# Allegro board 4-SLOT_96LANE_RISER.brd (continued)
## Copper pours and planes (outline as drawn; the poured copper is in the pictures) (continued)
P3V3 on TOP (solid shape): 289,96.77 289,96.74 288.85,96.23 288.99,95.71 289,95.69 289,95.5 288.68,95.18 288.66,95.18 287.85,94.27 288.55,93.28 288.57,93.27 288.88,92.96 288.88,92.7 288.88,91.95 288.75,91.82 284.3,91.82 284.23,91.9 284.23,93.37 286.72,95.86 286.72,96.82 286.97,97.08 288.7,97.08
P3V3 on TOP (solid shape): 288.62,76.33 288.62,74.91 288.61,74.86 288.57,74.84 287.86,74.01 288.34,73.04 288.35,73.04 288.86,72.53 288.86,71.5 288.74,71.37 282.91,71.37 282.84,71.44 282.84,71.92 285.97,75.06 285.98,75.06 286.21,75.06 286.46,75.31 286.46,75.33 286.66,75.7 286.65,76.12 286.65,76.13 286.97,76.45 286.97,76.5 286.99,76.56 287.05,76.58 288.37,76.58
P3V3 on TOP (solid shape): 288.88,56.26 288.88,55.8 288.87,55.79 288.85,55.57 288.87,55.36 288.88,55.35 288.88,54.61 288.82,54.55 288.79,54.55 287.88,53.8 288.36,52.72 288.37,52.71 288.88,52.2 288.88,51.94 288.88,51.18 288.75,51.05 282.91,51.05 282.78,51.18 282.78,51.69 285.81,54.72 285.84,54.72 286.53,55.09 286.63,55.86 286.63,55.9 286.65,55.94 287.1,56.39 288.75,56.39
P3V3 on BOTTOM (solid shape): 277.7,116.71 277.7,111.89 277.46,111.64 276.79,111.64 276.78,111.63 275.03,111.63 274.65,112.01 274.65,116.46 275.16,116.97 277.45,116.97
P3V3 on BOTTOM (solid shape): 115.42,39.07 115.56,38.94 116.47,38.94 116.52,38.92 116.54,38.86 116.54,37.25 115.75,36.46 114.35,36.46 114.21,36.6 114.21,37.69 114.69,38.18 114.69,38.56 114.62,38.63 114.62,39.02 114.72,39.12 115.36,39.12
P3V3 on BOTTOM (solid shape): 313.51,60.07 313.51,59.53 313.46,59.41 313.34,59.38 312.63,59.05 312.64,58.28 312.65,58.12 312.52,58.04 310.72,58.04 310.59,58.17 310.59,60.2 310.72,60.33 313.26,60.33
P3V3 on VCC1 (solid shape): outline of 26088 points within 1.02,5.69 321.03,117.23
P3V3_AGND on TOP (solid shape): 300.15,108.83 300.15,108.48 300.2,108.43 301.73,108.43 301.83,108.53 301.91,108.53 302.01,108.44 302.01,108.11 301.45,107.55 301.45,106.72 301.4,106.66 300.65,106.66 300.59,106.73 300.59,107.62 300.58,107.62 299.22,107.62 299.09,107.76 299.09,108.53 298.86,108.76 298.86,109.37 299.05,109.56 299.42,109.56
P3V3_AGND on BOTTOM (solid shape): 300.13,109.68 300.13,107.01 300.08,106.96 298.6,106.96 298.55,107.01 298.55,109.68 298.6,109.73 300.08,109.73
P3V3_BUF_VDDR on BOTTOM (solid shape): 312.07,54.69 312.07,52.88 311.89,52.7 311.02,52.7 310.67,53.06 310.61,53.06 310.59,53.07 310.33,53.14 310.07,53.06 309.2,53.06 308.84,53.42 308.84,54.1 308.97,54.23 310.85,54.23 311.35,54.74 312.02,54.74
P3V3_CLK_BUF_VDD on BOTTOM (solid shape): outline of 120 points within 304.24,55.88 312.37,58.29
P3V3_CLK_BUF_VDD on IN1 (solid shape): outline of 508 points within 301.96,48.39 313.53,58.83
P3V3_MB on TOP (solid shape): 289.24,9.42 289.24,6.97 288.19,5.92 288.19,1.57 288.15,1.54 287.52,1.54 287.47,1.56 287.45,1.61 287.45,5.64 287.21,5.64 287.21,1.61 287.19,1.56 287.13,1.54 286.63,1.54 286.57,1.56 286.55,1.61 286.55,6.11 287.05,6.6 287.05,8.84 287.86,9.65 289,9.65
P3V3_MB on BOTTOM (solid shape): 289.3,11.01 289.32,10.97 289.32,10.94 289.31,10.7 289.38,10.47 289.38,6.17 289.18,5.97 289.18,1.52 289.08,1.43 288.54,1.43 288.47,1.5 288.47,5.99 288.14,6.33 288.14,9.37 287.1,10.41 287.1,11.05 287.61,11.56 288.75,11.56
P3V3_OUT on TOP (solid shape): 281.84,115.78 281.84,110.41 282.09,110.16 282.83,110.16 282.91,110.08 282.91,104.52 281.84,103.45 281.84,103.44 281.56,103.16 278.66,103.16 278.56,103.26 278.56,104.69 278.7,105.04 278.56,105.39 278.56,106.92 278.7,107.27 278.56,107.63 278.56,109.16 278.7,109.51 278.56,109.86 278.56,116.53 278.79,116.76 280.86,116.76
P3V3_OUT on BOTTOM (solid shape): 281.23,116.56 281.23,115.6 281.38,115.44 281.69,115.44 282.03,115.1 282.03,114.89 282.04,114.88 282.04,113.61 283.25,112.4 283.25,110.83 283.38,110.69 284.53,110.69 284.61,110.62 284.61,105.85 283.41,104.65 282.95,104.65 281.76,103.47 279.52,103.47 279.52,103.47 278.83,103.47 278.8,103.48 278.78,103.49 278.64,103.63 278.64,104.79 278.65,104.81 278.7,105.04 278.65,105.27 278.64,105.29 278.64,107.02 278.65,107.04 278.7,107.27 278.65,107.51 278.64,107.52 278.64,109.26 278.65,109.28 278.7,109.51 278.65,109.74 278.64,109.76 278.64,116.66 278.74,116.76 281.03,116.76
P3V3_STBY on TOP (solid shape): 291.92,50.67 291.92,49.91 291.8,49.78 289.26,49.78 289.13,49.91 289.13,50.67 289.26,50.8 291.8,50.8
P3V3_STBY on TOP (solid shape): 291.92,91.44 291.92,90.55 291.8,90.42 289.38,90.42 289.21,90.6 289.21,91.52 289.26,91.57 291.8,91.57
P3V3_STBY on TOP (solid shape): 287.48,103.45 287.48,100.3 287.25,100.08 286.44,100.08 286.2,100.32 286.2,102.18 286.01,102.37 286.01,103.48 286.04,103.52 287.42,103.52
P3V3_STBY on TOP (solid shape): 298.53,93.45 298.53,90.04 298.42,89.94 297.35,89.94 297.33,89.92 297.26,89.92 297.13,90.04 297.13,91.84 297.13,93.45 297.31,93.62 298.35,93.62
P3V3_STBY on TOP (solid shape): 286.84,63.14 286.93,63.14 287.22,63.14 287.33,63.04 287.33,62.31 287.52,62.12 287.52,61.03 287.52,61.02 287.52,59.47 287.35,59.31 286.36,59.31 286.16,59.51 286.16,62.15 286.41,62.41 286.41,63.09 286.46,63.14 286.76,63.14
P3V3_STBY on TOP (solid shape): 286.84,42.94 286.93,42.95 287.2,42.95 287.31,42.84 287.31,41.9 287.48,41.73 287.48,39.37 287.22,39.12 286.36,39.12 286.16,39.32 286.16,41.73 286.34,41.91 286.34,42.17 286.34,42.88 286.41,42.95 286.76,42.95
P3V3_STBY on TOP (solid shape): 287.08,83.48 287.22,83.46 287.37,83.48 287.38,83.48 287.69,83.48 287.73,83.44 287.73,82.68 287.73,81.41 287.48,81.15 287.48,80.01 287.22,79.76 286.46,79.76 286.21,80.01 286.21,81.92 286.72,82.42 286.72,82.68 286.72,82.68 286.72,83.44 286.76,83.48 287.07,83.48
P3V3_STBY on IN3 (solid shape): outline of 10865 points within 283.41,28.7 298.91,103
P3V3_STBY_AGND on TOP (solid shape): 312.8,87.2 313.97,87.2 314.2,86.97 314.2,86.61 314.07,86.48 313.94,86.48 313.79,86.33 313.79,85.62 313.66,85.49 312.78,85.49 312.65,85.62 312.65,86.59 312.29,86.94 311.78,86.94 311.68,87.04 311.68,87.32 311.81,87.45 312.55,87.45
P3V3_STBY_AGND on BOTTOM (solid shape): 311.47,89.26 311.53,89.23 311.55,89.18 311.55,88.9 311.56,88.8 311.6,88.71 311.61,88.69 311.61,88.54 311.65,88.5 311.65,88.44 312.57,88.44 312.64,88.38 312.64,86.36 312.6,86.35 312.6,86.16 312.57,86.1 312.52,86.08 311.52,86.08 311.52,85.22 311.5,85.16 311.45,85.14 311.3,85.14 311.28,85.17 311.28,86.01 311.27,86.02 311.27,86.16 311.28,86.23 311.28,89.25 311.28,89.26
P3V3_STBY_MB on BOTTOM (solid shape): 288.75,15.62 288.75,14.22 288.49,13.97 286.34,13.97 286.08,14.22 286.08,15.37 286.46,15.75 288.62,15.75
P3V3_STBY_MB on IN1 (solid shape): outline of 3470 points within 286.34,14.61 317.07,47.75
P3V3_STBY_OUT on TOP (solid shape): 299.82,92.89 299.82,91.57 299.82,91.44 299.87,91.39 300.4,91.39 300.96,90.83 300.96,85.32 300.47,84.82 299.12,84.82 298.88,85.06 298.88,92.86 298.99,92.96 299.75,92.96
P3V3_STBY_OUT on BOTTOM (solid shape): 300.35,92.1 300.35,90.78 300.44,90.7 301.19,90.7 301.22,90.67 301.22,89.72 302.76,88.19 302.76,82.33 302.46,82.04 299.29,82.04 298.88,82.45 298.88,92.1 299.04,92.25 300.2,92.25
P12V on TOP (solid shape): 286.84,115.7 286.84,113.88 286.72,113.75 284.98,113.75 284.43,114.3 284.43,115.7 284.68,115.95 286.59,115.95
P12V on TOP (solid shape): 55.41,37.2 55.41,35.57 55.31,35.47 54.9,35.47 54.85,35.42 54.85,34.69 54.77,34.61 53.32,34.61 52.94,34.99 52.94,37.02 53.28,37.36 55.25,37.36
P12V on TOP (solid shape): 292.43,104.57 292.43,104.16 293.09,103.5 293.09,103.5 293.14,103.45 295.68,103.45 297.49,101.65 297.49,94.18 296.88,93.57 296.88,92 296.88,91.95 296.75,91.82 293.35,91.82 293.27,91.9 293.27,93.45 293.28,93.48 293.34,93.53 293.4,93.59 293.46,93.64 293.51,93.71 293.56,93.78 293.6,93.85 293.63,93.93 293.66,94.01 293.67,94.09 293.68,94.18 293.68,94.26 293.67,94.34 293.65,94.42 293.63,94.5 293.6,94.58 293.56,94.65 293.51,94.72 293.46,94.79 293.4,94.85 293.33,94.9 293.27,94.95 293.22,94.97 292.93,95.26 292.93,95.36 296.68,95.36 296.68,97.07 294.98,97.07 294.98,95.36 292.93,95.36 292.93,99.33 293.57,99.97 293.57,100.31 293.6,100.36 293.63,100.43 293.66,100.51 293.67,100.59 293.68,100.67 293.68,100.76 293.67,100.84 293.66,100.92 293.63,101 293.6,101.07 293.57,101.12 293.57,101.14 293.52,101.21 293.46,101.28 293.4,101.35 293.33,101.4 293.28,101.43 293.19,101.52 293.09,101.52 293.04,101.54 292.96,101.56 292.87,101.57 292.79,101.57 292.7,101.56 292.62,101.54 292.56,101.52 291.72,101.52 291.24,102.01 291.24,104.47 291.42,104.65 292.36,104.65
P12V on TOP (solid shape): outline of 495 points within 292.94,30.73 305.39,84.45
P12V on TOP (solid shape): outline of 629 points within 1.45,85.59 18.37,106.36
P12V on BOTTOM (solid shape): 89.36,41.15 89.36,40.13 88.34,39.12 87.07,39.12 86.82,39.37 86.82,41.4 86.95,41.53 88.98,41.53
P12V on BOTTOM (solid shape): 287.99,116.71 287.99,116.08 287.86,115.95 287.49,115.95 286.99,115.45 286.99,114.13 286.78,113.92 284.81,113.92 284.43,114.3 284.43,116.46 284.81,116.84 287.86,116.84
P12V on BOTTOM (solid shape): 23.42,90.84 24.16,90.84 24.64,90.36 25.48,90.36 25.94,89.91 26.8,89.91 26.85,89.86 26.85,89.47 26.71,89.33 22.89,89.33 22.56,89.66 22.56,90.68 22.77,90.89 23.37,90.89
P12V on BOTTOM (solid shape): 25.91,101.61 25.99,101.61 26,101.6 26.18,101.6 26.18,101.59 26.78,101.59 26.83,101.57 26.85,101.51 26.85,101.32 26.54,101.02 24.46,101.02 23.01,101.02 22.81,101.22 22.81,101.73 22.94,101.85 24.46,101.85 24.59,101.98 25.55,101.98
P12V on IN1 (solid shape): outline of 946 points within 1.4,86.54 14.2,106.78
P12V on VCC (solid shape): outline of 20463 points within 1.02,22.61 321.03,117.23
P12V on IN4 (solid shape): outline of 147445 points within 1.14,20.32 320.9,117.1
P12V_MB on TOP (solid shape): 294.77,8.84 294.77,6.22 295.19,5.8 295.19,1.51 295.15,1.47 294.52,1.47 294.47,1.5 294.45,1.55 294.45,5.64 294.21,5.64 294.21,1.55 294.19,1.5 294.13,1.47 293.55,1.47 293.5,1.5 293.47,1.55 293.47,5.89 292.86,6.5 292.86,8.81 293.07,9.02 294.59,9.02
P12V_MB on BOTTOM (solid shape): 295.2,11.15 295.2,7.25 295.2,7.14 295.2,1.52 295.1,1.43 294.52,1.43 294.47,1.45 294.45,1.5 294.45,5.64 294.21,5.64 294.21,1.5 294.19,1.45 294.13,1.43 293.54,1.43 293.48,1.45 293.46,1.5 293.46,5.9 293.45,5.9 293.45,6.25 292.86,6.83 292.86,11.18 293.19,11.51 294.84,11.51
P12V_PSU on TOP (solid shape): 303.15,93.07 303.15,90.37 303.1,90.32 302.06,90.32 301.96,90.42 301.96,90.84 301.96,90.87 301.98,90.89 302.11,91.2 302.02,91.52 302.01,91.54 302.01,91.72 302.02,91.73 302.02,92.93 302.29,93.19 303.02,93.19
P12V_PSU on TOP (solid shape): 10.96,88.94 11.54,88.36 12.36,88.39 15.06,88.39 15.32,88.14 15.32,87 15.19,86.87 14.22,86.87 14.22,86.79 14.17,86.74 14.17,85.93 13.72,85.47 8.59,85.47 7.7,86.36 7.7,89.66 8.21,90.17 9.73,90.17
P12V_PSU on BOTTOM (solid shape): 303.18,92.84 303.18,91.49 302.92,91.24 302.29,91.24 302.16,91.36 302.16,91.54 301.88,91.82 301.88,92.63 302.39,93.14 302.87,93.14
P12V_PSU on IN2 (solid shape): outline of 7571 points within 7.7,13.72 303.86,90.17
P12V_PSU on IN3 (solid shape): 11.38,88.39 12.52,88.39 13.3,87.62 13.3,85.86 13.16,85.72 9.6,85.72 7.7,87.63 7.7,89.53 8.33,90.17 9.6,90.17
P12V_PSU on IN3: 299.39,26.34 300.36,27.3 302.22,27.3 302.34,27.24 302.36,27.1 302.71,26.59 303.08,27.09 303.09,27.19 303.17,27.27 303.23,27.3 315.29,27.3 315.93,27.94 315.93,28.13 315.95,28.19 315.96,28.2 316.07,28.38 316.07,28.59 316.08,28.78 315.99,28.95 315.95,28.99 315.93,29.05 315.93,31.89 315.99,32.02 316.14,32.03 316.66,32.38 316.14,32.74 315.99,32.75 315.93,32.88 315.93,33.34 315.99,33.46 316.12,33.48 316.61,33.85 316.12,34.22 315.99,34.24 315.93,34.37 315.93,48.47 308.9,55.5 305,55.5 303.7,56.8 303.69,56.82 303.62,56.91 303.53,56.98 303.52,56.99 303.48,57.02 299.92,57.02 299.57,57.38 299.57,83.9 300.76,85.09 300.76,92.56 301.45,93.24 303.38,93.24 304.18,92.44 304.18,89.45 305.28,88.34 306,88.34 307.47,86.87 307.47,83.57 310.77,80.26 313.92,80.26 314.63,80.98 314.63,83.01 314.99,83.36 315.27,83.36 315.85,82.78 315.85,79.58 315.04,78.77 312.14,78.77 304.5,71.12 304.5,65.41 307.82,62.08 318.62,62.08 320.63,60.07 320.63,26.16 316.43,21.97 299.92,21.97 299.39,22.5
VCC_P5V_1 on BOTTOM (solid shape): 31.52,102.25 31.52,101.82 30.3,100.6 28.89,100.6 28.33,101.16 28.33,101.51 28.35,101.57 28.4,101.59 28.96,101.59 29.04,101.67 29.04,101.97 29.14,102.07 29.32,102.07 29.37,102.02 29.37,101.92 29.38,101.92 29.42,101.88 29.42,101.71 29.52,101.61 30.28,101.61 30.96,102.3 31.47,102.3
VCC_P5V_2 on BOTTOM (solid shape): 31.6,90.41 31.6,90.03 31.4,89.83 31.17,89.83 30.3,88.97 29.25,88.97 28.9,89.32 28.48,89.32 28.33,89.47 28.33,89.83 28.35,89.88 28.4,89.91 29,89.91 29,90.32 29.09,90.41 29.29,90.41 29.44,90.26 29.44,90.11 29.62,89.93 30.38,89.93 30.95,90.49 31.52,90.49
TPS7A37_OUT on BOTTOM (solid shape): 112.13,39.12 113.02,39.12 113.07,39.09 113.09,39.04 113.09,38.71 112.74,38.35 112.28,38.35 112.05,38.13 112.05,36.58 111.97,36.5 111.11,36.5 111.09,36.52 111.09,37.31 110.78,37.62 109.28,37.62 109.26,37.64 108.57,37.64 108.56,37.63 107.86,37.63 107.73,37.75 107.73,39 107.96,39.23 108.25,39.23 108.27,39.24 110.76,39.24 111.09,39.57 111.67,39.57
VR_P0V9_12VIN on TOP (solid shape): 27.93,101.75 27.93,101.1 28.45,100.57 30.74,100.57 30.98,100.33 30.98,99.95 30.98,99.91 30.99,99.85 30.99,99.45 31.05,99.4 31.88,99.4 31.93,99.38 31.95,99.33 31.95,97.83 31.88,97.75 29.28,97.75 29.24,97.75 29.15,97.73 27.26,97.73 26.96,98.03 23.78,98.03 23.17,97.42 23.17,97.4 23.17,97.4 23.17,95.48 23.17,95.48 23.17,93.47 23.83,92.82 23.83,91.08 23.17,90.42 22.56,90.42 21.79,89.66 21.79,89.03 22.57,88.25 25.97,88.25 26.14,88.43 26.14,90.18 26.3,90.34 27.66,90.34 27.8,90.2 27.8,89.51 28.42,88.89 30.76,88.89 30.98,88.67 30.98,88.27 30.98,88.22 30.99,88.17 30.99,87.77 31.05,87.72 31.95,87.72 31.98,87.7 31.98,86.21 31.85,86.08 28.75,86.08 28.72,86.04 27.26,86.04 26.96,86.35 23.81,86.35 23.19,85.72 19.45,85.72 18.87,86.3 18.87,89.74 19.28,90.14 19.28,98.27 19.43,98.42 20.25,98.42 21.76,99.94 25.97,99.94 26.14,100.11 26.14,101.87 26.3,102.02 27.66,102.02
VR_P0V9_12VIN on BOTTOM (solid shape): 28.24,99.53 31.04,99.53 31.68,98.89 31.68,98.44 31.44,98.2 30.62,98.2 29.56,97.14 28.91,97.14 28.33,97.73 27.26,97.73 26.96,98.03 23.7,98.03 23.56,98.17 23.56,99.93 23.62,99.99 27.79,99.99
VR_P0V9_12VIN on BOTTOM (solid shape): 28.83,87.95 30.94,87.95 31.68,87.21 31.68,86.73 31.49,86.54 30.19,86.54 30.18,86.53 30.02,86.53 29.59,86.1 27.21,86.1 26.96,86.35 23.4,86.35 23.32,86.42 23.32,88.2 23.43,88.3 28.48,88.3
VR_P0V9_SW1 on TOP (solid shape): 39.7,98.07 39.7,96.82 39.4,96.82 39.4,96.19 39.7,96.19 39.7,94.41 38.9,93.61 34,93.61 33.81,93.8 33.81,94.79 33.74,94.86 29.97,94.86 29.87,94.96 29.87,97.25 30.02,97.4 34.37,97.4 34.42,97.35 34.42,97.15 34.6,96.97 35.86,96.97 36.43,97.54 36.43,98.04 36.48,98.09 39.68,98.09
VR_P0V9_SW1 on BOTTOM (solid shape): 37.14,96.49 37.14,95.45 36.68,95 35.89,95 35.51,95.38 34.11,95.38 33.99,95.5 33.99,96.52 34.11,96.65 36.98,96.65
VR_P0V9_SW2 on TOP (solid shape): 39.7,86.39 39.7,85.14 39.4,85.14 39.4,84.51 39.7,84.51 39.7,82.72 38.9,81.92 34,81.92 33.81,82.11 33.81,83.11 33.74,83.18 29.97,83.18 29.87,83.28 29.87,85.56 30.02,85.72 34.37,85.72 34.42,85.66 34.42,85.46 34.6,85.28 35.86,85.28 36.43,85.85 36.43,86.36 36.48,86.41 39.68,86.41
VR_P0V9_SW2 on BOTTOM (solid shape): 37.03,84.76 37.03,83.72 36.63,83.31 35.89,83.31 35.51,83.69 34.11,83.69 33.99,83.82 33.99,84.84 34.11,84.96 36.83,84.96
VR_P0V9A_PVIN on TOP (solid shape): outline of 88 points within 56.17,34.56 67.25,41.57
VR_P0V9A_PVIN on BOTTOM (solid shape): 65.01,41.78 65.01,40.43 65.57,39.87 66.46,39.87 66.5,39.86 66.52,39.85 66.53,39.83 66.54,39.79 66.54,39.49 66.54,39.45 66.55,39.36 66.57,39.28 66.59,39.2 66.63,39.12 66.67,39.05 66.7,39.02 66.7,38.08 65.12,36.5 63.25,36.5 62.82,36.07 57.61,36.07 57.35,36.32 57.35,37.26 64.32,37.26 64.33,37.21 64.34,37.15 64.36,37.1 64.39,37.05 64.42,37.01 64.46,36.97 64.51,36.94 64.56,36.91 64.61,36.89 64.66,36.88 64.72,36.88 64.78,36.89 64.83,36.9 64.88,36.92 64.93,36.95 64.97,36.99 65.01,37.03 65.04,37.07 65.06,37.13 65.08,37.18 65.09,37.23 65.09,37.29 65.08,37.34 65.06,37.4 65.04,37.45 65.01,37.5 64.97,37.54 64.93,37.57 64.88,37.6 64.83,37.62 64.78,37.64 64.72,37.64 64.66,37.64 64.61,37.63 64.56,37.61 64.51,37.59 64.46,37.56 64.42,37.52 64.39,37.47 64.36,37.42 64.34,37.37 64.33,37.32 64.32,37.26 57.35,37.26 57.35,37.72 57.48,37.85 61.46,37.85 62.14,38.52 62.14,40.15 61.52,40.77 61.52,42.02 61.76,42.26 62.57,42.26 63.02,42.71 64.09,42.71
VR_P0V9A_SW on TOP (solid shape): 62.6,44.84 62.6,44.42 62.9,44.11 66.69,44.11 66.74,44.09 66.76,44.04 66.76,42 66.74,41.98 63.74,41.98 62.7,40.93 62.5,40.73 58.43,40.73 58.36,40.81 58.36,44.69 58.57,44.9 62.54,44.9
VR_P1V8A_PVIN on TOP (solid shape): 84.3,41.88 84.3,41.18 84.42,41.07 85.18,41.07 85.37,41.26 85.34,41.29 85.34,41.62 85.44,41.72 86.64,41.72 87.05,41.31 87.05,39.27 86.8,39.02 85.2,39.02 84.84,38.66 82.04,38.66 81.92,38.79 81.92,42.21 82.12,42.42 83.77,42.42
VR_P1V8A_PVIN on BOTTOM (solid shape): 83.77,42.2 83.77,42.2 83.77,41.63 84.41,41 86.26,41 86.44,40.82 86.44,39.29 86.23,39.09 85.68,39.09 85.41,39.36 84.04,39.36 83.64,39.75 83.16,39.75 82.2,40.72 82.2,40.84 82.22,40.86 82.22,42.43 82.37,42.58 83.39,42.58
VR_P1V8A_SW on TOP (solid shape): 86.19,38.36 86.69,38.36 86.95,38.1 86.95,35.05 86.82,34.92 84.91,34.92 84.79,35.05 84.79,36.32 84.25,36.86 81.97,36.86 81.89,36.94 81.89,38.26 81.99,38.36 86.18,38.36
VR_P3V3_PVIN on TOP (solid shape): outline of 85 points within 287.58,108.85 298.32,115.7
VR_P3V3_PVIN on BOTTOM (solid shape): outline of 87 points within 287.61,109.51 298.65,116.84
VR_P3V3_STBY_PVIN on TOP (solid shape): outline of 140 points within 303.42,88.41 310.61,93.01
VR_P3V3_STBY_PVIN on BOTTOM (solid shape): 308.08,93.19 308.08,91.11 308.2,90.98 309.17,90.98 309.25,91.06 309.25,92 309.37,92.13 310.85,92.13 311.02,91.95 311.02,89.36 311.02,89.36 311.02,88.06 311,88 310.95,87.98 309.45,87.98 309.07,88.37 309.07,88.52 308.32,89.27 308.32,89.39 308.31,89.4 308.31,89.81 308.18,89.94 305.36,89.94 305.23,90.07 305.23,90.47 305.32,90.56 305.35,90.58 305.38,90.58 305.5,90.57 305.61,90.6 305.62,90.6 305.87,90.6 306.02,90.75 306.02,93.09 306.27,93.34 307.93,93.34
VR_P3V3_STBY_SW on BOTTOM (solid shape): 308.68,88.21 308.71,88.21 308.73,88.19 309.19,87.73 309.34,87.73 309.35,87.73 310.95,87.73 311.02,87.66 311.02,86.26 311,86.23 309.35,86.23 308.58,85.47 308.58,84.86 308.53,84.81 306.43,84.81 306.37,84.86 306.37,85.13 306.38,85.14 306.4,85.29 306.38,85.44 306.37,85.45 306.37,87.07 306.38,87.09 306.43,87.3 306.38,87.51 306.37,87.52 306.37,88.16 306.43,88.21
VR_P3V3_SW on BOTTOM (solid shape): 294.08,110.46 294.08,109.86 294.82,109.13 298.15,109.13 298.17,109.1 298.17,107.07 298.15,107.02 298.09,106.99 294.31,106.99 294.11,106.79 294.11,106.3 293.98,106.17 289.81,106.17 289.74,106.25 289.74,110.23 289.74,110.24 289.74,110.41 289.89,110.57 293.98,110.57

Small or netless copper shapes (teardrops, artwork), in the pictures only: 200 on TOP, 3 on BOTTOM, 1 on GND, 2 on IN1, 1 on GND1, 2 on IN2, 1 on VCC, 1 on VCC1, 2 on IN3, 1 on GND2, 2 on IN4, 1 on GND3

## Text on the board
Ref Des/Silkscreen Bottom: A
Ref Des/Silkscreen Top: A | B | F | E | G | C | D | PCB-4RSMOXLC-P0 REV:P0
User.26: FIGURE | SIZE | 10.0 | 16.0 | 22.0 | 24.0 | 28.0 | 41.0 | 44.0 | 48.0 | 174.0 | 221.0 | 47.0 | 95.0 | 119.0 | 158.0 | DRILL CHART: TOP to BOTTOM | ALL UNITS ARE IN MILS | TOLERANCE | +3.0/-3.0 | +4.0/-0.0 | +2.0/-2.0 | PLATED | NON-PLATED | QTY | 226 | 4210 | 46 | 80 | 30 | 2 | 658 | 76 | 4 | 8 | 6
